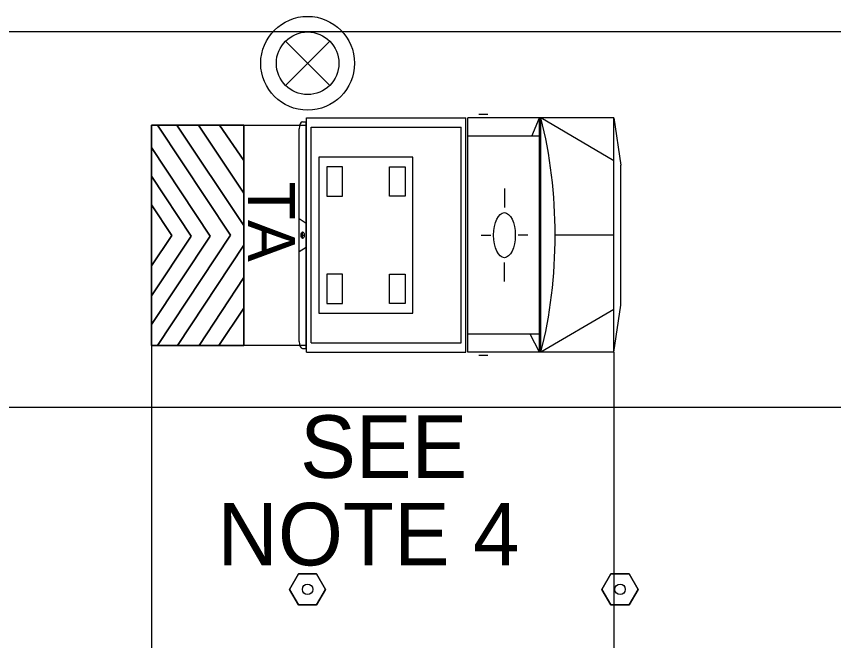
# Model space of a CAD drawing. Extents: x 99958 to 100136, y 99935 to 100013.
# Drawn here: x 100030.117 to 100031.164, y 99975.337 to 99976.136 of the extents above; entities that cross this region are included whole.
import ezdxf

# ---------------------------------------------------------------- set-up
doc = ezdxf.new("R2010")
doc.units = 0
for name, color, linetype in [('RD_MK_LineEdgeWhite', 7, 'Continuous'), ('RD_MK_LineLane', 7, 'Continuous'), ('TR_WZ_TrafficSafetyDrum', 7, 'Continuous'), ('TR_WZ_TransportableAttenuator', 7, 'Continuous'), ('TR_WZ_TubularMarker', 7, 'Continuous'), ('TR_WZ_WorkZoneDetails', 7, 'Continuous'), ('TR_WZ_WorkZoneTextCurrent', 7, 'Continuous')]:
    doc.layers.add(name, color=color, linetype=linetype)

msp = doc.modelspace()

# ---------------------------------------------------------------- linework, layer by layer
at = {"layer": 'RD_MK_LineEdgeWhite'}
msp.add_line((100021.7753, 99975.6357), (100035.62, 99975.6357), dxfattribs=at)
at = {"layer": 'RD_MK_LineLane'}
msp.add_lwpolyline([(100035.62, 99976.1157), (100021.7753, 99976.1157)], dxfattribs=at)
at = {"layer": 'TR_WZ_TrafficSafetyDrum'}
for p, q in [((100030.462, 99976.104), (100030.5186, 99976.0474)), ((100030.5186, 99976.104), (100030.462, 99976.0474))]:
    msp.add_line(p, q, dxfattribs=at)
for radius in [0.06, 0.06, 0.04]:
    msp.add_circle((100030.4903, 99976.0757), radius, dxfattribs=at)
at = {"layer": 'TR_WZ_TransportableAttenuator'}
for p, q in [((100030.4891, 99976.0058), (100030.6927, 99976.0058)), ((100030.4891, 99975.7058), (100030.4891, 99976.0058)), ((100030.6927, 99975.7058), (100030.6927, 99976.0058)), ((100030.6955, 99975.7058), (100030.6955, 99976.0058)), ((100030.8824, 99976.0058), (100030.6955, 99976.0058)), ((100030.7209, 99976.0099), (100030.7097, 99976.0099)), ((100030.7774, 99975.9825), (100030.7872, 99976.0058)), ((100030.7872, 99975.7058), (100030.7872, 99976.0058)), ((100030.7889, 99975.7058), (100030.7889, 99976.0058)), ((100030.8824, 99975.9508), (100030.7889, 99976.0058)), ((100030.8824, 99975.7058), (100030.8824, 99976.0058)), ((100030.8824, 99976.0058), (100030.8915, 99975.9452)), ((100030.3231, 99975.9965), (100030.298, 99975.9965)), ((100030.298, 99975.9965), (100030.3918, 99975.8555)), ((100030.3918, 99975.8555), (100030.298, 99975.9965)), ((100030.298, 99975.9965), (100030.3231, 99975.9965)), ((100030.4085, 99975.8681), (100030.3231, 99975.9965)), ((100030.3231, 99975.9965), (100030.4085, 99975.8681)), ((100030.3777, 99975.9965), (100030.3507, 99975.9965)), ((100030.3507, 99975.9965), (100030.4085, 99975.9096)), ((100030.4085, 99975.9096), (100030.3507, 99975.9965)), ((100030.3507, 99975.9965), (100030.3777, 99975.9965)), ((100030.4085, 99975.9511), (100030.3777, 99975.9965)), ((100030.3777, 99975.9965), (100030.4085, 99975.9511)), ((100030.4891, 99975.9962), (100030.4085, 99975.9962)), ((100030.4085, 99975.9962), (100030.4085, 99975.7146)), ((100030.4796, 99975.7198), (100030.4796, 99975.9917)), ((100030.484, 99976.0008), (100030.4884, 99976.0008)), ((100030.4884, 99975.7107), (100030.4884, 99976.0008)), ((100030.4891, 99975.7151), (100030.4891, 99975.9962)), ((100030.4949, 99975.7177), (100030.4949, 99975.9938)), ((100030.4949, 99975.9938), (100030.6869, 99975.9938)), ((100030.6869, 99975.7177), (100030.6869, 99975.9938)), ((100030.7872, 99975.9825), (100030.6955, 99975.9825)), ((100030.3656, 99975.8546), (100030.2903, 99975.9678)), ((100030.2903, 99975.9678), (100030.2903, 99975.931)), ((100030.2903, 99975.931), (100030.2903, 99975.9678)), ((100030.2903, 99975.9678), (100030.3656, 99975.8546)), ((100030.4085, 99975.9096), (100030.4085, 99975.9511)), ((100030.4085, 99975.9511), (100030.4085, 99975.9096)), ((100030.8915, 99975.7663), (100030.8915, 99975.9452)), ((100030.2903, 99975.931), (100030.3414, 99975.8542)), ((100030.3414, 99975.8542), (100030.2903, 99975.931)), ((100030.7424, 99975.9152), (100030.7423, 99975.891)), ((100030.3164, 99975.8553), (100030.2903, 99975.8945)), ((100030.2903, 99975.8945), (100030.2903, 99975.8165)), ((100030.2903, 99975.8945), (100030.3164, 99975.8553)), ((100030.2903, 99975.8165), (100030.2903, 99975.8945)), ((100030.4796, 99975.8769), (100030.4884, 99975.8712)), ((100030.4085, 99975.843), (100030.4085, 99975.8681)), ((100030.4085, 99975.8681), (100030.4085, 99975.843)), ((100030.2903, 99975.8165), (100030.3164, 99975.8553)), ((100030.3164, 99975.8553), (100030.2903, 99975.8165)), ((100030.3918, 99975.8555), (100030.2981, 99975.7146)), ((100030.2981, 99975.7146), (100030.3918, 99975.8555)), ((100030.482, 99975.8557), (100030.4861, 99975.8557)), ((100030.484, 99975.8515), (100030.484, 99975.86)), ((100030.7125, 99975.8555), (100030.725, 99975.8556)), ((100030.7284, 99975.8563), (100030.7284, 99975.8563)), ((100030.7722, 99975.8555), (100030.7597, 99975.8556)), ((100030.8824, 99975.8557), (100030.8073, 99975.8557)), ((100030.2903, 99975.7414), (100030.3656, 99975.8546)), ((100030.3656, 99975.8546), (100030.2903, 99975.7414)), ((100030.3414, 99975.8542), (100030.2903, 99975.7779)), ((100030.2903, 99975.7779), (100030.3414, 99975.8542)), ((100030.3236, 99975.7146), (100030.4085, 99975.843)), ((100030.4085, 99975.843), (100030.3236, 99975.7146)), ((100030.4796, 99975.8346), (100030.4884, 99975.8402)), ((100030.7424, 99975.7963), (100030.7423, 99975.8205)), ((100030.4085, 99975.8015), (100030.3513, 99975.7146)), ((100030.3513, 99975.7146), (100030.4085, 99975.8015)), ((100030.4085, 99975.7623), (100030.4085, 99975.8015)), ((100030.4085, 99975.8015), (100030.4085, 99975.7623)), ((100030.2903, 99975.7779), (100030.2903, 99975.7414)), ((100030.2903, 99975.7414), (100030.2903, 99975.7779)), ((100030.3768, 99975.7146), (100030.4085, 99975.7623)), ((100030.4085, 99975.7623), (100030.3768, 99975.7146)), ((100030.8824, 99975.7607), (100030.7889, 99975.7058)), ((100030.8824, 99975.7058), (100030.8915, 99975.7663)), ((100030.7872, 99975.729), (100030.6955, 99975.729)), ((100030.7872, 99975.7058), (100030.7753, 99975.729)), ((100030.2981, 99975.7146), (100030.3236, 99975.7146)), ((100030.3236, 99975.7146), (100030.2981, 99975.7146)), ((100030.3513, 99975.7146), (100030.3768, 99975.7146)), ((100030.3768, 99975.7146), (100030.3513, 99975.7146)), ((100030.4891, 99975.7146), (100030.4085, 99975.7146)), ((100030.484, 99975.7107), (100030.4884, 99975.7107)), ((100030.4949, 99975.7177), (100030.6869, 99975.7177)), ((100030.4891, 99975.7058), (100030.6927, 99975.7058)), ((100030.8824, 99975.7058), (100030.6955, 99975.7058)), ((100030.7209, 99975.7015), (100030.7097, 99975.7015))]:
    msp.add_line(p, q, dxfattribs=at)
for points in [[(100030.4085, 99975.9965), (100030.2903, 99975.9965), (100030.2903, 99975.7146), (100030.4085, 99975.7146)], [(100030.5049, 99975.7557), (100030.6252, 99975.7557), (100030.6252, 99975.9557), (100030.5049, 99975.9557)], [(100030.515, 99975.9057), (100030.535, 99975.9057), (100030.535, 99975.9432), (100030.515, 99975.9432)], [(100030.6152, 99975.9057), (100030.5951, 99975.9057), (100030.5951, 99975.9432), (100030.6152, 99975.9432)], [(100030.515, 99975.7682), (100030.535, 99975.7682), (100030.535, 99975.8057), (100030.515, 99975.8057)], [(100030.6152, 99975.7682), (100030.5951, 99975.7682), (100030.5951, 99975.8057), (100030.6152, 99975.8057)]]:
    msp.add_lwpolyline(points, close=True, dxfattribs=at)
msp.add_lwpolyline([(100030.4085, 99975.7146), (100030.2903, 99975.7146), (100030.2903, 99975.9965), (100030.4085, 99975.9962)], dxfattribs=at)
for centre, major_axis, start_param, end_param in [((100030.6553, 99975.8558), (0, 0.3148), 4.215667, 5.208926), ((100030.484, 99975.9917), (0, 0.00916), 0, 1.570796), ((100030.484, 99975.7198), (0, -0.00916), 4.712389, 6.283185)]:
    msp.add_ellipse(centre, major_axis=major_axis, ratio=0.482618, start_param=start_param, end_param=end_param, dxfattribs=at)
for centre, major_axis in [((100030.7423, 99975.8557), (0, -0.0289)), ((100030.484, 99975.8557), (0, -0.00423))]:
    msp.add_ellipse(centre, major_axis=major_axis, ratio=0.482618, dxfattribs=at)
at = {"layer": 'TR_WZ_TubularMarker'}
for points in [[(100030.4672, 99975.4024), (100030.4787, 99975.4224), (100030.5018, 99975.4224), (100030.5134, 99975.4024), (100030.5018, 99975.3824), (100030.4787, 99975.3824)], [(100030.8672, 99975.4024), (100030.8787, 99975.4224), (100030.9018, 99975.4224), (100030.9134, 99975.4024), (100030.9018, 99975.3824), (100030.8787, 99975.3824)]]:
    msp.add_lwpolyline(points, close=True, dxfattribs=at)
for points in [[(100030.4787, 99975.3824), (100030.5018, 99975.3824), (100030.5134, 99975.4024), (100030.5018, 99975.4224), (100030.4787, 99975.4224), (100030.4672, 99975.4024), (100030.4787, 99975.3824)], [(100030.8787, 99975.3824), (100030.9018, 99975.3824), (100030.9134, 99975.4024), (100030.9018, 99975.4224), (100030.8787, 99975.4224), (100030.8672, 99975.4024), (100030.8787, 99975.3824)]]:
    msp.add_lwpolyline(points, dxfattribs=at)
for centre in [(100030.4903, 99975.4024), (100030.8903, 99975.4024)]:
    msp.add_circle(centre, 0.00667, dxfattribs=at)
at = {"layer": 'TR_WZ_WorkZoneDetails'}
for p, q in [((100030.2903, 99975.7146), (100030.2903, 99974.9957)), ((100030.8824, 99975.7058), (100030.8824, 99974.9957))]:
    msp.add_line(p, q, dxfattribs=at)

# ---------------------------------------------------------------- texts
at = {"layer": 'TR_WZ_TransportableAttenuator'}
msp.add_text('TA', height=0.06013, rotation=270, dxfattribs=at).set_placement((100030.414, 99975.9243))
at = {"layer": 'TR_WZ_WorkZoneTextCurrent'}
for s, p in [('SEE', (100030.4807, 99975.5451)), ('NOTE 4', (100030.3751, 99975.4331))]:
    msp.add_text(s, height=0.08, dxfattribs=at).set_placement(p)

doc.saveas('drawing.dxf')
